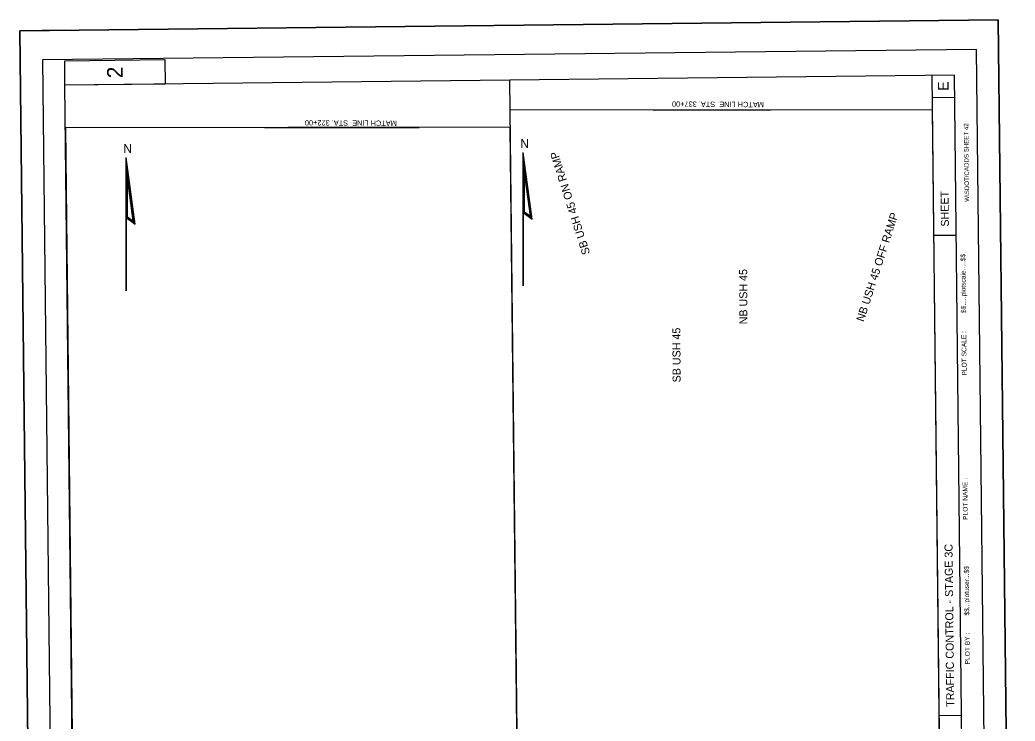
# Model space of a CAD drawing. Extents: x 359851 to 360969, y 155041 to 156753.
# Drawn here: x 359851 to 360969, y 155965 to 156753 of the extents above; entities that cross this region are included whole.
import ezdxf

# ---------------------------------------------------------------- set-up
doc = ezdxf.new("R2010")
doc.units = 0
for name, color, linetype in [('Default', 7, 'Continuous'), ('P_ALI_20', 7, 'Continuous'), ('P_ALI_200_Sta', 7, 'Continuous'), ('P_ALI_20_PIData', 7, 'Continuous'), ('P_ALI_20_Tic', 7, 'Continuous'), ('P_ALI_50_Equation', 7, 'Continuous'), ('P_ALI_50_PIData', 7, 'Continuous'), ('P_ALI_50_Tic', 7, 'Continuous')]:
    doc.layers.add(name, color=color, linetype=linetype)

msp = doc.modelspace()

# ---------------------------------------------------------------- linework, layer by layer
msp.add_lwpolyline([(359869.4, 155041.2), (359850.5, 156741), (360950.5, 156753.3), (360969.3, 155053.4), (359869.4, 155041.2)])
at = {"layer": 'Default'}
for points in [[(360418.2, 155151.9), (360893.2, 155152.2), (360876.6, 156652.1), (360401.5, 156651.8)], [(360418.2, 155151.9), (360893.2, 155152.2), (360876.6, 156652.1), (360401.5, 156651.8)], [(360418.2, 155151.9), (360893.2, 155152.2), (360876.6, 156652.1), (360401.5, 156651.8)], [(359914.2, 155507.8), (360143.8, 155510.4), (360146.5, 155107.5), (360418.7, 155110.5), (360401.8, 156632.5), (359901.7, 156632.1)], [(359914.2, 155507.8), (360143.8, 155510.4), (360146.5, 155107.5), (360418.7, 155110.5), (360401.8, 156632.5), (359901.7, 156632.1)], [(359914.2, 155507.8), (360143.8, 155510.4), (360146.5, 155107.5), (360418.7, 155110.5), (360401.8, 156632.5), (359901.7, 156632.1)]]:
    msp.add_lwpolyline(points, close=True, dxfattribs=at)
at = {"layer": 'P_ALI_20'}
for p, q in [((360950.5, 156753.3), (360900.5, 156752.7)), ((360951, 156703.3), (360950.5, 156753.3)), ((359900.5, 156741.6), (359850.5, 156741)), ((359851.1, 156691.1), (359850.5, 156741)), ((360901.1, 156691), (359901.2, 156679.9)), ((360418.7, 155110.5), (360401.2, 156685.4)), ((360893.6, 155115.8), (360876.1, 156690.7)), ((360918.6, 155116.1), (360901.1, 156691)), ((359918.7, 155105), (359901.2, 156679.9)), ((360901.4, 156666), (360876.4, 156665.7)), ((360903.1, 156511), (360878.1, 156510.7)), ((360909.1, 155971), (360884.1, 155970.7))]:
    msp.add_line(p, q, dxfattribs=at)
msp.add_lwpolyline([(359901.2, 156679.9), (359900.9, 156707.4), (360013.4, 156708.6), (360013.7, 156681.1)], close=True, dxfattribs=at)
at = {"layer": 'P_ALI_200_Sta'}
msp.add_line((360418.7, 155110.5), (360401.2, 156685.4), dxfattribs=at)
at = {"layer": 'P_ALI_20_PIData'}
for p, q in [((360426.3, 156529.2), (360416.3, 156604.2)), ((360416.3, 156536.7), (360416.3, 156604.2)), ((359980, 156523.7), (359970, 156598.7)), ((359970, 156531.2), (359970, 156598.7)), ((360417.1, 156537.1), (360417.1, 156592.9)), ((360425.4, 156530.9), (360417.1, 156592.9)), ((359970.8, 156531.6), (359970.8, 156587.4)), ((359979, 156525.4), (359970.8, 156587.4)), ((360417.8, 156537.5), (360417.8, 156581.6)), ((360424.4, 156532.6), (360417.8, 156581.6)), ((359971.5, 156532), (359971.5, 156576.1)), ((359978, 156527.1), (359971.5, 156576.1)), ((360416.3, 156536.7), (360426.3, 156529.2)), ((360416.3, 156454.2), (360416.3, 156536.7)), ((360416.6, 156454.2), (360416.6, 156536.5)), ((360417.1, 156537.1), (360425.4, 156530.9)), ((360417.8, 156537.5), (360424.4, 156532.6)), ((359970, 156531.2), (359980, 156523.7)), ((359970, 156448.7), (359970, 156531.2)), ((359970.3, 156448.7), (359970.3, 156531)), ((359970.8, 156531.6), (359979, 156525.4)), ((359971.5, 156532), (359978, 156527.1))]:
    msp.add_line(p, q, dxfattribs=at)
for points in [[(360416.3, 156604.2), (360416.3, 156604.2)], [(359970, 156598.6), (359970, 156598.6)]]:
    msp.add_lwpolyline(points, dxfattribs=at)
at = {"layer": 'P_ALI_20_Tic'}
msp.add_lwpolyline([(359869.4, 155041.2), (359850.5, 156741), (360950.5, 156753.3), (360969.3, 155053.4)], close=True, dxfattribs=at)
at = {"layer": 'P_ALI_50_Equation'}
for p, q in [((360562.4, 156651.9), (360694.7, 156652)), ((360125.6, 156632.3), (360299.3, 156632.4))]:
    msp.add_line(p, q, dxfattribs=at)
at = {"layer": 'P_ALI_50_Tic'}
for points in [[(360969.3, 155053.4), (360950.5, 156753.3), (359850.5, 156741), (359869.4, 155041.2)], [(360944.2, 155065.1), (360925.8, 156720), (359875.9, 156708.3), (359894.3, 155053.4)]]:
    msp.add_lwpolyline(points, close=True, dxfattribs=at)

# ---------------------------------------------------------------- texts
at = {"layer": 'P_ALI_20'}
for s, height, p in [('2', 17.5, (359966.1, 156687.8)), ('E', 12, (360894.7, 156673.5)), ('WISDOT/CADDS SHEET 42', 5, (360917.7, 156548.8)), ('SHEET ', 9, (360895, 156520.9)), ('$$.....plotscale.....$$', 5.4, (360914.1, 156423.6)), ('PLOT SCALE : ', 5.4, (360914.9, 156353.4)), ('PLOT NAME :                      ', 5.4, (360916.2, 156191.1)), ('TRAFFIC CONTROL - STAGE 3C', 9, (360901, 155980.9)), ('$$...plotuser...$$', 5.4, (360917.9, 156083.6)), ('PLOT BY :', 5.4, (360918.5, 156028.6))]:
    msp.add_text(s, height=height, rotation=90.6368, dxfattribs=at).set_placement(p)
at = {"layer": 'P_ALI_20_PIData'}
for p in [(359966.9, 156603.6), (360413.2, 156609.2)]:
    msp.add_text('N', height=10, dxfattribs=at).set_placement(p)
at = {"layer": 'P_ALI_50_PIData'}
for s, height, rotation, p in [('MATCH LINE  STA. 337+00', 6, 179.6332, (360687, 156661)), ('MATCH LINE  STA. 322+00', 6, 179.6332, (360274.3, 156640)), ('SB USH 45 ON RAMP', 9, 107.621, (360491.7, 156490.8)), ('NB USH 45 OFF RAMP', 9, 72.1375, (360799.1, 156413.3)), ('NB USH 45', 9, 90.2702, (360668.4, 156411)), ('SB USH 45', 9, 90.2285, (360593.3, 156345.7))]:
    msp.add_text(s, height=height, rotation=rotation, dxfattribs=at).set_placement(p)

doc.saveas('drawing.dxf')
